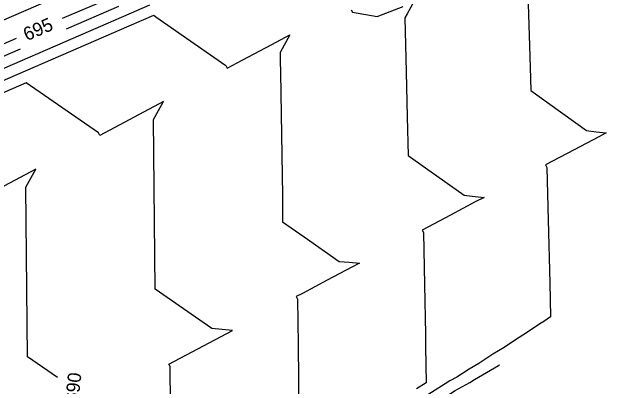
# Model space of a CAD drawing. Extents: x 1487507 to 1489130, y 497211 to 499439.
# Drawn here: x 1487940.5 to 1488046.9, y 498440 to 498507 of the extents above; entities that cross this region are included whole.
import ezdxf

# ---------------------------------------------------------------- set-up
doc = ezdxf.new("R2010")
doc.units = 0
for name, color, linetype in [('Prop CMT Ditch DDE', 7, 'Continuous'), ('Prop Drainage Ditch Flow Line', 7, 'Continuous'), ('Prop Drainage Structure Pipe Outlet Channel Detail CELL', 7, 'Continuous')]:
    doc.layers.add(name, color=color, linetype=linetype)

msp = doc.modelspace()

# ---------------------------------------------------------------- linework, layer by layer
at = {"layer": 'Prop CMT Ditch DDE'}
for points in [[(1487892.42, 498485.4), (1487956.82, 498513.36)], [(1488012.56, 498509.07), (1488011.27, 498506.67), (1488010.86, 498506), (1488011.09, 498496.33), (1488011.27, 498488.22), (1488011.42, 498481.31), (1488014.56, 498479.08), (1488021.44, 498474.17), (1488022.9, 498474.03), (1488025.03, 498473.81), (1488023.45, 498472.98), (1488019.03, 498470.64), (1488013.94, 498467.94), (1488014.18, 498467.5), (1488014.35, 498458.1), (1488014.51, 498449.26), (1488014.55, 498447.05), (1488014.65, 498440.59), (1488012.9, 498439.48)], [(1487896.16, 498478.33), (1487960.56, 498506.29), (1487965.16, 498508.29)], [(1487950.29, 498504.01), (1487959.62, 498508.06)], [(1488001.21, 498507.43), (1488001.44, 498506.99), (1488005.86, 498506.2), (1488010.56, 498508.02)], [(1488032.94, 498508.49), (1488033.29, 498497.15), (1488033.41, 498492.95), (1488036.81, 498490.49), (1488043.33, 498485.76), (1488045.07, 498485.57), (1488046.86, 498485.37), (1488045.55, 498484.67), (1488041.13, 498482.33), (1488036, 498479.62), (1488036.24, 498479.18), (1488036.5, 498469.73), (1488036.5, 498469.71), (1488036.79, 498458.48), (1488036.93, 498452.39), (1488035.74, 498451.58), (1488035.02, 498451.12), (1488032.42, 498449.38), (1488030.82, 498448.37), (1488028.61, 498446.92), (1488026.59, 498445.68), (1488024.07, 498444.05), (1488022.33, 498443.03), (1488020.12, 498441.61), (1488018.91, 498440.94), (1488018.07, 498440.4), (1488013.83, 498437.71)], [(1487897.09, 498476.56), (1487961.49, 498504.52), (1487965.89, 498506.43), (1487966.29, 498506.15), (1487975.26, 498499.89), (1487978.79, 498497.42), (1487979.02, 498496.98), (1487981.71, 498498.4), (1487987.01, 498501.21), (1487990.27, 498502.93), (1487988.52, 498499.74), (1487988.54, 498498.31), (1487988.58, 498496.1), (1487988.75, 498485.09), (1487988.91, 498474.11), (1487988.96, 498469.43), (1487992.81, 498466.74), (1487999.09, 498462.34), (1488000.88, 498462.18), (1488002.73, 498462.01), (1488001.36, 498461.28), (1487996.94, 498458.94), (1487992.52, 498456.6), (1487991.41, 498456.01), (1487991.64, 498455.57), (1487991.73, 498447.41), (1487991.91, 498428.56)], [(1487870.49, 498463.42), (1487872.92, 498465.17), (1487875.69, 498467.14), (1487877.07, 498468.13), (1487879.9, 498470.12), (1487881.24, 498471.07), (1487884.08, 498473.13), (1487885.38, 498474.05), (1487888.18, 498476.24), (1487889.45, 498477.16), (1487892.76, 498478.62), (1487895.22, 498480.09), (1487942.04, 498500.42)], [(1487969.05, 498416.46), (1487968.8, 498443.48), (1487968.56, 498443.92), (1487979.99, 498449.97), (1487976.31, 498450.28), (1487966.14, 498457.34), (1487965.84, 498487.74), (1487967.65, 498490.96), (1487956.22, 498484.91), (1487955.99, 498485.35), (1487943.04, 498494.34), (1487918.73, 498483.78)]]:
    msp.add_lwpolyline(points, dxfattribs=at)
at = {"layer": 'Prop Drainage Ditch Flow Line'}
for points in [[(1487958.69, 498509.83), (1487949.5, 498505.84)], [(1487941.24, 498502.25), (1487894.29, 498481.86), (1487891.32, 498480.08), (1487888.28, 498478.75), (1487886.76, 498477.64), (1487884.2, 498475.64), (1487882.64, 498474.54), (1487880.05, 498472.66), (1487878.46, 498471.53), (1487875.89, 498469.72), (1487874.26, 498468.55), (1487871.74, 498466.76), (1487869.64, 498465.25)], [(1487948.66, 498441.52), (1487943.28, 498445.25), (1487942.99, 498475.64), (1487944.8, 498478.86), (1487933.37, 498472.81), (1487933.14, 498473.25), (1487920.19, 498482.24), (1487919.52, 498481.95)], [(1487981.82, 498415.09), (1488002.06, 498427.9), (1488006.29, 498430.58), (1488010.53, 498433.26), (1488014.77, 498435.95), (1488019, 498438.63), (1488019.85, 498439.17), (1488022.49, 498440.65), (1488023.31, 498441.18), (1488027.58, 498443.68), (1488027.63, 498443.71), (1488027.81, 498443.81)]]:
    msp.add_lwpolyline(points, dxfattribs=at)

# ---------------------------------------------------------------- texts
at = {"layer": 'Prop Drainage Structure Pipe Outlet Channel Detail CELL'}
for s, rotation, p in [('695', 23.4722, (1487943.18, 498501.78)), ('690', 83.8678, (1487952.39, 498436.95))]:
    msp.add_text(s, height=2.4, rotation=rotation, dxfattribs=at).set_placement(p)

doc.saveas('drawing.dxf')
